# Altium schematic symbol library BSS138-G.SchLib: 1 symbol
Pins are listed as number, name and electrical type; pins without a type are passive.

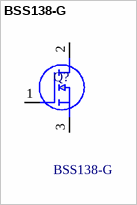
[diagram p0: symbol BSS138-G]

## BSS138-G
designator Q?
MOSFET FET 50V 3.5 OHM; Manufacturer_Name: onsemi; Geometry.Height: 1.11mm
footprint SOT96P237X111-3N
pins: 1 G, 2 D, 3 S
